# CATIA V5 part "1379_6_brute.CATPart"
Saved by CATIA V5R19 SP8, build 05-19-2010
Part number: 6
Bounding box of the stored display mesh (mm): x -5 to 2.367, y 21.633 to 51.486, z 6.5 to 38.993
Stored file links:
  J:\IAO_IFMA\1379_6_brute.CATPart
  J:\IAO_IFMA\1379_Squelette.CATPart
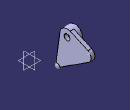
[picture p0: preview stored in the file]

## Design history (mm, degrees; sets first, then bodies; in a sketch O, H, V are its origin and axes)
Body1 (main body)
  Point1 to Point5: stored without definition
  Sketch1 on yz-plane, origin (0, 0, 0), H (0, 1, 0), V (0, 0, 1)
    point P1 (22.9967, 9.1243)
    line L1 (22.9967, 9.1243) -> (26.0455, 33.7376)
    arc A1 centre (32, 33) radius 6 from (26.0455, 33.7376) to (34.4288, 38.4864) cw
    point P3 (32, 33)
    line L2 (34.4288, 38.4864) -> (48.8216, 32.1148)
    arc A2 centre (47, 28) radius 4.5 from (48.8216, 32.1148) to (49.4405, 24.2193) cw
    point P6 (47, 28)
    construction line L3 (45.544, 23.7421) -> (36.0819, 26.9777)
    construction arc A3 centre (35.1112, 24.1391) radius 3 from (36.0819, 26.9777) to (32.3694, 25.3566) ccw
    construction line L4 (32.3694, 25.3566) -> (24.924, 8.5897)
    point P11 (24.924, 8.5897)
    construction arc A4 centre (24, 9) radius 1.011 from (24.924, 8.5897) to (24.5483, 8.1506) cw
    point P12 (24, 9)
    reference projected point E1 (32, 33) from Point2
    reference projected point E2 (24, 9) from Point4
    reference projected point E3 (47, 28) from Point5
    circle A5 centre (32, 33) radius 2.5
    line L5 (49.4405, 24.2193) -> (24.5483, 8.1506)
    construction arc A6 centre (47, 28) radius 4.5 from (45.544, 23.7421) to (49.4405, 24.2193) ccw
    arc A7 centre (24, 9) radius 1.011 from (24.5483, 8.1506) to (22.9967, 9.1243) cw
    radius A1 = 6
    radius A2 = 4.5
    distance P11 P1 = 2
    radius A3 = 3
    angle L2 L3 = 5
    length L3 = 10
    radius A5 = 2.5
    tangency: A1 L1, A2 L2, A3 L3, A4 L4, A1 L2, L4 A3, L1 A4, A2 L3, L5 A2, L5 A4, A6 L3
    coincidence: P3 E1, P12 E2, P6 E3, A4 A7
  Pad1: profile Sketch1, direction (1, 0, 0), length 1.5, opposite side length 1.5
  Point6: stored without definition
  Sketch2 on yz-plane, origin (0, 0, 0), H (0, 1, 0), V (0, 0, 1)
    arc A1 centre (24, 9) radius 2.5 from (24, 11.5) to (24, 6.5) ccw
    point P1 (24, 9)
    reference projected point E1 (24, 9) from Point6
    axis line L1 (24, 11.5) -> (24, 6.5)
    point P3 (24, 6.5)
    line L2 (24, 11.5) -> (24, 6.5)
    point P4 (24, 6.5)
    radius A1 = 2.5
    coincidence: P1 E1, L1 P1, P4 A1, L2 L1, P3 P4
    vertical: L1 V
  Shaft1: profile Sketch2, axis Sketch2.L1, angle 360
  Point7: stored without definition
  Sketch3 on start face of Pad1, origin (-1.5, 0, 0), H (0, 1, 0), V (0, 0, 1)
    circle A1 centre (47, 28) radius 1.5
    point P1 (47, 28)
    reference projected point E1 (47, 28) from Point10
    radius A1 = 1.5
    coincidence: P1 E1
  Pad2: profile Sketch3, direction (-1, 0, 0), length 2
  Sketch4 on start face of Pad1, origin (-1.5, 0, 0), H (0, -1, 0), V (0, 0, 1)
    circle A1 centre (-32, 33) radius 6
    reference projected arc E1 centre (-32, 33) radius 6 from (-26.0455, 33.7376) to (-34.4288, 38.4864) ccw from edge [start face of Pad1 | face of Pad1 from Sketch1.A1]
    circle A2 centre (-32, 33) radius 2.5
    reference projected circle E2 centre (-32, 33) radius 2.5 from edge [face of Pad1 from Sketch1.A5 | start face of Pad1]
    reference projected circle E3 centre (-32, 33) radius 2.5 from edge [face of Pad1 from Sketch1.A5 | start face of Pad1]
    coincidence: A1 E1, A2 E3
    concentricity: A2 E2
  Pad3: profile Sketch4, direction (-1, 0, 0), length 3.5
  Point8: type Center, Curve edge [face of Pad2 from Sketch3.A1 | start face of Pad1]
  Point9: type Center, Curve face of Shaft1 from Sketch2.A1
  Point10: stored without definition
